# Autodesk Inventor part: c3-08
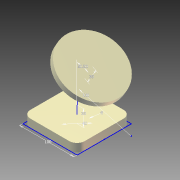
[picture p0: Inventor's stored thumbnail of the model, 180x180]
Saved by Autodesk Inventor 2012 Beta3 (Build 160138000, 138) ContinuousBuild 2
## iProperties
Created: 2010-11
Part Number: c3-08
Material: Cast Iron
Document SubType Name: Modeling
Designer: Beta-8540w
Density: 7.25 g/cm^3
Mass: 1087.5 g
Surface Area: 260 cm^2
Volume: 150 cm^3
Author: Beta-8540w
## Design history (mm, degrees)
sketch "Sketch1"
  geometry: L1 (-50, -50)-(50, -50); L2 (50, -50)-(50, 50); L3 (50, 50)-(-50, 50); L4 (-50, 50)-(-50, -50); C1 r 20 at (0, 0); C2 r 28 at (0, 0); 3 further points
  constraints: 8 end point, 3 perpendicular, 2 centre point, 2 coincident, 2 midpoint, 1 horizontal, 1 horizontal alignment, 1 parallel, 1 vertical alignment
  dimensions: "Width" = 100 distance of L1.start L1.end; "d6" = 40 diameter of C1; "d7" = 8 radial gap between concentric circles of C2 C1
extrude "Extrusion1" new body sketch "Sketch1" distance "d3" = 15; taper "d4" = 0 deg
fillet "Fillet1" dims "d5" = 14
sketch "Sketch2"
  geometry: L1 (0, 0)-(0, 30); L2 (-13.397, 80)-(-28.397, 105.981); A1 r 100 centre (-100, 30) between (0, 30) and (-13.397, 80)
  constraints: 4 end point, 2 point on circle, 2 tangent, 1 centre point, 1 vertical
  dimensions: "d8" = 30 distance of L1.start L1.end; "d9" = 100 radius of A1; "d10" = 30 distance of L2.start L2.end; "d11" = 30 deg angle of L2 L1
sketch "Sketch3"
  geometry: L1 (-13.397, 80)-(-28.397, 105.981) reference; L2 (-28.397, 105.981)-(-76.029, 78.481); L3 (-76.029, 78.481)-(-71.029, 69.821); L4 (-71.029, 69.821)-(-23.397, 97.321); L5 (-23.397, 97.321)-(-28.397, 105.981); 1 further point
  constraints: 8 end point, 2 parallel, 2 perpendicular
  dimensions: "d16" = 10 distance of L3.end L2.end; "d17" = 110 diameter of L3 L5
revolve "Revolution1" sketch "Sketch3" stored, may be unused: angle "d18" = 90 deg
body "Solid1"
